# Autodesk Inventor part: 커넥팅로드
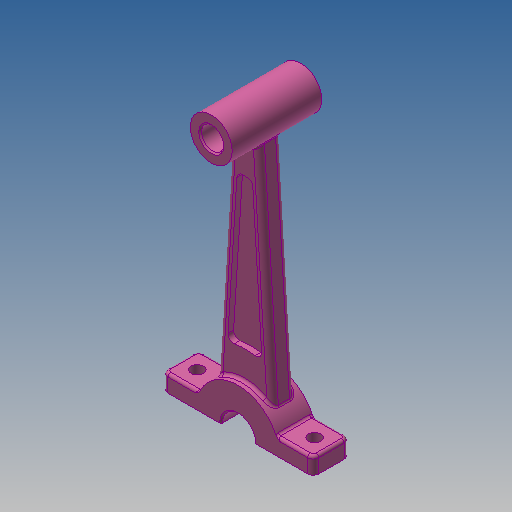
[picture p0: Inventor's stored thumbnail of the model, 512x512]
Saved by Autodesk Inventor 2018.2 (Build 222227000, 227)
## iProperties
Created: 2016-11
Part Number: 커넥팅로드
Material: 알루미늄 6061
Document SubType Name: Modeling
Designer: mduedu
Density: 2.71 g/cm^3
Mass: 44.549 g
Surface Area: 86.7069 cm^2
Volume: 16.4387 cm^3
Appearance: 분홍색
Author: mduedu
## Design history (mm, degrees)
sketch "스케치1" dims "d0" = 30, "d3" = 15
  geometry: L1 (0, 0)-(0, 96); L2 (-5, 90.41)-(-10, 11.18); L3 (5, 90.41)-(10, 11.18); C1 r 6 at (0, 0); C2 r 4 at (0, 96); 3 further points
  constraints: 6 end point, 4 coincident, 2 centre point, 2 symmetric about line, 1 vertical, 6 other
  dimensions: "d1" = 12 diameter of C1; "d2" = 8 diameter of C2; "d4" = 96 distance of L1.start L1.end; "d6" = 10 distance from line of L1 L2.end; "d7" = 5 distance from line of L1 L2.start
extrude "돌출1" new body sketch "스케치1" stored distance "d8" = 13; taper "d9" = 0 deg
extrude "돌출2" join sketch "스케치1" stored distance "d10" = 32; taper "d11" = 0 deg
sketch "스케치2"
  geometry: L1 (5, 90.41)-(10, 11.18) reference; L2 (-5, 90.41)-(-10, 11.18) reference; A1 r 7.5 centre (0, 96) between (5, 90.41) and (-5, 90.41) reference; A2 r 15 centre (0, 0) between (10, 11.18) and (-10, 11.18) reference
extrude "돌출3" join sketch "스케치2" stored distance "d12" = 8; taper "d13" = 0 deg
sketch "스케치3"
  geometry: L1 (-2.732, 78.715)-(-6.171, 24.226); L2 (2.732, 78.715)-(6.171, 24.226); L3 (0, 78.5)-(0, 25); A1 r 17.5 centre (0, 96) between (-2.732, 78.715) and (2.732, 78.715); A2 r 25 centre (0, 0) between (6.171, 24.226) and (-6.171, 24.226); 9 further points; 2 other entities
  constraints: 6 end point, 6 point on circle, 2 centre point, 1 symmetric about line, 1 vertical alignment, 6 other
  dimensions: "d18" = 10 dimension on A1; "d19" = 10 dimension on A2; "d20" = 3 dimension on L1
extrude "돌출4" cut sketch "스케치3" distance "d21" = 2; taper "d22" = 0 deg
fillet "모깎기1" dims "d23" = 2
fillet "모깎기2" dims "d24" = 2
fillet "모깎기3" dims "d25" = 1
chamfer "모따기1" distance "d26" = 0.5; stored, may be unused: second distance "d27" = 2, angle "d28" = 45 deg
sketch "스케치4"
  geometry: L1 (-27, -6)-(-13.748, -6); L2 (27, -6)-(27, 6); L3 (27, 6)-(13.748, 6); L4 (-27, 6)-(-27, -6); L5 (-27, -6)-(27, 6); L6 (27, -6)-(-27, 6); L7 (-13.748, 6)-(-27, 6); L8 (13.748, 6)-(-13.748, 6); L9 (13.748, -6)-(27, -6); L10 (-13.748, -6)-(13.748, -6); A1 r 15 centre (0, 0) between (-13.748, 6) and (13.748, 6) reference; 1 further point
  constraints: 20 end point, 10 parallel, 4 point on circle, 3 horizontal, 3 perpendicular, 2 midpoint
  dimensions: "d29" = 54 distance of L1.start L2.start; "d31" = 12 distance of L2.start L2.end
extrude "돌출5" join sketch "스케치4" stored distance "d32" = 0; taper "d33" = 0 deg
fillet "모깎기4" dims "d34" = 2
fillet "모깎기5" dims "d35" = 1
fillet "모깎기6" dims "d36" = 1
sketch "스케치5"
  geometry: L1 (1, 0)-(1, 9) reference; L2 (-18.5, 20.5)-(-33.5, 20.5) reference; L3 (-33.5, -11.5)-(-18.5, -11.5) reference; L4 (-26, 20.5)-(-26, -11.5); 3 further points
  constraints: 2 end point, 2 midpoint, 1 horizontal alignment, 1 symmetric about line
  dimensions: "d37" = 6 distance from line of point (-5, 4.5) L1
feature "분할1"
sketch "스케치7"
  geometry: 2 further points
  constraints: 2 other
hole "구멍2" sketch "스케치7" at (-47, 4.5), (-5, 4.5) diameter "d45" = 4.5; stored, may be unused: countersink angle "d49" = 90 deg, drill point angle "d51" = 0 deg; dims "d46" = 6, "d47" = 4, "d48" = 2, "d50" = 8
node "솔리드1"
mirror "대칭1"
other parameters: "d16" = 4, "d17" = 4
